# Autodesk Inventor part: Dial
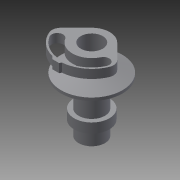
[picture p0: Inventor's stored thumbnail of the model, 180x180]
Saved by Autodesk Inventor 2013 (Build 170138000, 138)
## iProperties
Shininess: 64.0
Length Units: 11272
Angle Units: 11279
Time Units: 11290
Mass Units: 11286
Length Display Precision: 3
Angle Display Precision: 2
Compacted: True
Created: 2001-11
Part Number: Dial
Document SubType Name: Modeling
Designer: Autodesk, Inc.
Mass: 1.02961 g
Surface Area: 19.0281 cm^2
Volume: 1.02961 cm^3
Density: 1 g/cm^3
Material: Generic
Density: 0.0
Volumn: 0.0
Area: 0.0
PropertySet Name: Model Information
Control State: 0
Master: False
Checked Out: False
Author: Autodesk, Inc.
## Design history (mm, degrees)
sketch "Sketch1"
  geometry: L1 (120.263, 98.09)-(121.533, 98.09); L2 (121.533, 100.63)-(121.533, 98.09); L3 (121.533, 100.63)-(125.343, 100.63); L4 (125.343, 101.458)-(125.343, 100.63); L5 (119.755, 103.715)-(125.343, 101.458); L6 (119.755, 106.472)-(119.755, 103.715); L7 (119.755, 106.472)-(125.851, 106.472); L8 (125.851, 106.472)-(125.851, 109.012); L9 (116.453, 109.012)-(125.851, 109.012); L10 (116.453, 109.012)-(116.453, 86.66); L11 (116.453, 86.66)-(117.215, 86.66); L12 (117.215, 86.66)-(117.215, 85.644); L13 (117.215, 85.644)-(120.263, 85.644); L14 (120.263, 89.708)-(120.263, 85.644); L15 (120.263, 89.708)-(121.533, 89.708); L16 (121.533, 92.502)-(121.533, 89.708); L17 (120.263, 92.502)-(121.533, 92.502); L18 (120.263, 98.09)-(120.263, 92.502); L19 (116.453, 109.012)-(116.453, 86.66)
  constraints: 38 end point, 9 vertical, 8 horizontal, 2 collinear, 1 other
  dimensions: "d1" = 9.398 distance of L9.start L8.end; "d3" = 22.352 distance of L9.start L10.end; "d5" = 2.54 distance of L7.end L8.end; "d11" = 10.922 vertical distance of L9.start L1.end; "d13" = 8.382 vertical distance of L9.start L3.end; "d15" = 16.51 vertical distance of L16.start L8.end; "d17" = 19.304 vertical distance of L14.start L8.end; "d19" = 1.016 distance of L11.end L12.end; "d23" = 8.89 horizontal distance of L10.end L3.end; "d25" = 0.762 distance of L10.end L11.end; "d27" = 3.048 distance of L12.end L13.end; "d51" = 6.604 diameter of L6 L10
revolve "RevolutionFull1" sketch "Sketch1" stored, may be unused: angle "d28" = 360 deg
sketch "Sketch2"
  geometry: C1 r 3.302 at (0, 0) reference; A1 r 5.588 centre (0, 0) between (-4.761, -2.925) and (5.042, -2.408); A2 r 1.651 centre (6.532, -3.12) between (7.607, -1.867) and (5.042, -2.408); A3 r 1.651 centre (6.532, -3.12) between (8.022, -3.832) and (7.607, -1.867); A4 r 8.89 centre (0, 0) between (-7.575, -4.654) and (8.022, -3.832); A5 r 1.651 centre (-6.168, -3.79) between (-7.335, -2.622) and (-7.575, -4.654); A6 r 1.651 centre (-6.168, -3.79) between (-4.761, -2.925) and (-7.335, -2.622)
  constraints: 12 point on circle, 6 centre point, 5 tangent, 4 concentric
  dimensions: "d34" = 12.7 horizontal distance of A6.centre A3.centre; "d36" = 5.588 radius of A1; "d38" = 8.89 radius of A4
extrude "ExtrusionToFace1" cut sketch "Sketch2" stored distance "d39" = 3.302; taper "d40" = 0 deg
sketch "Sketch3"
  geometry: L1 (25.051, 17.256)-(-16.734, 17.256); L2 (25.051, -5.225)-(25.051, 17.256); L3 (25.051, -5.225)-(10.165, -5.225); L4 (3.682, 3.682)-(9.59, -2.226); L5 (-3.682, 3.682)-(-9.632, -2.268); L6 (-16.734, -6.364)-(-10.09, -5.233); L7 (-16.734, 17.256)-(-16.734, -6.364); C1 r 9.398 at (0, 0) reference; A1 r 2.721 centre (7.666, -4.15) between (10.165, -5.225) and (9.59, -2.226); A2 r 5.207 centre (0, 0) between (3.682, 3.682) and (-3.682, 3.682); A3 r 2.54 centre (-7.836, -4.064) between (-9.632, -2.268) and (-10.09, -5.233)
  constraints: 14 end point, 6 point on circle, 4 tangent, 3 centre point, 2 horizontal, 2 vertical, 1 concentric
extrude "ExtrusionBlind1" cut sketch "Sketch3" distance "d41" = 2.54; taper "d42" = 0 deg
sketch "Sketch4"
  geometry: L1 (-1.536, -9.906)-(0.457, -9.906); L2 (0.457, -9.906)-(0.734, -9.369); L3 (-1.536, -9.906)-(-2.352, -9.099); A1 r 9.398 centre (0, 0) between (-9.214, -1.85) and (9.214, -1.85) reference
  constraints: 6 end point, 2 point on circle, 1 horizontal, 1 other
  dimensions: "d44" = 9.906 dimension on L1.start
extrude "ExtrusionToPlane1" join sketch "Sketch4" stored distance "d45" = 3.302; taper "d46" = 0 deg
extrude "ExtrusionThru1" cut stored distance "d49" = 3.302; taper "d50" = 0 deg
  node "Sketch5" dims "d48" = 6.35
fillet "Fillet1" dims "d52" = 2.54
body "Solid1"
other parameters: "d0" = 9.398 (derived), "d2" = 22.352 (derived), "d4" = 2.54 (derived), "d6" = 5.08 (derived), "d8" = 6.604 (derived), "d10" = 10.922 (derived), "d12" = 8.382 (derived), "d14" = 16.51 (derived), "d16" = 19.304 (derived), "d18" = 1.016 (derived), "d20" = 158 deg (derived), "d22" = 8.89 (derived), "d24" = 0.762 (derived), "d26" = 3.048 (derived), "d29" = 0, "d30" = 0, "d31" = 0, "d32" = 0, "d33" = 12.7 (derived), "d35" = 5.588 (derived), "d37" = 8.89 (derived), "d43" = 9.906 (derived), "d47" = 6.35 (derived)
